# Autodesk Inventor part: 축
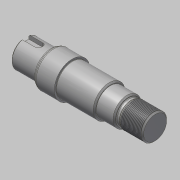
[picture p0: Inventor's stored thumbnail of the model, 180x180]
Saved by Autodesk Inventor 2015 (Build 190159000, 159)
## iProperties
Created: 2019-05
Part Number: 축
Material: 강철, 연강
Document SubType Name: Modeling
Designer: mduedu
Density: 1 g/cm^3
Appearance: 강철
Author: mduedu
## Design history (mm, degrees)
sketch "스케치1"
  geometry: L1 (0, 0)-(20, 0); L2 (20, 0)-(20, 11); L3 (20, 11)-(0, 11); L4 (0, 11)-(0, 0); L5 (20, 0)-(37, 0); L6 (37, 0)-(37, 14); L7 (37, 14)-(20, 14); L8 (20, 14)-(20, 0); L9 (37, 0)-(67, 0); L10 (67, 0)-(67, 12.5); L11 (67, 12.5)-(37, 12.5); L12 (37, 12.5)-(37, 0); L13 (67, 0)-(81, 0); L14 (81, 0)-(81, 11); L15 (81, 11)-(67, 11); L16 (67, 11)-(67, 0); L17 (81, 0)-(102, 0); L18 (102, 0)-(102, 10); L19 (102, 10)-(81, 10); L20 (81, 10)-(81, 0)
  constraints: 40 end point, 10 parallel, 5 horizontal, 5 perpendicular
  dimensions: "d0" = 102 distance between parallel lines of L18 L4; "d2" = 21 distance of L18.end L19.end; "d3" = 14 distance of L14.end L15.end; "d4" = 30 distance of L10.end L11.end; "d5" = 17 distance of L6.end L7.end; "d6" = 22 diameter of L3 L1; "d7" = 28 diameter of L7 L5; "d8" = 25 diameter of L11 L9; "d9" = 22 diameter of L15 L13; "d10" = 20 diameter of L19 L17
revolve "회전1" sketch "스케치1" stored, may be unused: angle "d11" = 90 deg
chamfer "모따기1" distance "d12" = 2.34; stored, may be unused: second distance "d13" = 2, angle "d14" = 30 deg
fillet "모깎기1" dims "d15" = 2, "d16" = 1
fillet "모깎기2" dims "d17" = 0.3
chamfer "모따기2" distance "d18" = 1; stored, may be unused: second distance "d19" = 2, angle "d20" = 30 deg
sketch "스케치2"
  geometry: L1 (102, -10)-(81, -10) reference; L2 (81, -10)-(81, -11) reference; L3 (81, -11)-(67, -11) reference; L4 (67, -11)-(67, -11.5) reference; L5 (67, -11.5)-(66, -12.5) reference; L6 (66, -12.5)-(37.3, -12.5) reference; L7 (37, -12.8)-(37, -14) reference; L8 (37, -14)-(22.876, -14) reference; L9 (21.876, -13.732)-(20.5, -12.938) reference; L10 (20, -12.072)-(20, -11) reference; L11 (20, -11)-(0, -11) reference; L12 (0, -11)-(0, 11) reference; L13 (0, 11)-(20, 11) reference; L14 (20, 11)-(20, 12.072) reference; L15 (20.5, 12.938)-(21.876, 13.732) reference; L16 (22.876, 14)-(37, 14) reference; L17 (37, 14)-(37, 12.8) reference; L18 (37.3, 12.5)-(66, 12.5) reference; L19 (66, 12.5)-(67, 11.5) reference; L20 (67, 11.5)-(67, 11) reference; L21 (67, 11)-(81, 11) reference; L22 (81, 11)-(81, 10) reference; L23 (81, 10)-(102, 10) reference; L24 (102, 10)-(102, -10) reference; L25 (0, 0)-(102, 0); L26 (81, 10)-(84.726, 10); L27 (83.34, 9.2)-(81, 9.2); L28 (81, 9.2)-(81, 10); L29 (84.726, 10)-(83.34, 9.2); A1 r 0.3 centre (37.3, -12.8) between (37.3, -12.5) and (37, -12.8) reference; A2 r 2 centre (22.876, -12) between (21.876, -13.732) and (22.876, -14) reference; A3 r 1 centre (21, -12.072) between (20, -12.072) and (20.5, -12.938) reference; A4 r 1 centre (21, 12.072) between (20.5, 12.938) and (20, 12.072) reference; A5 r 2 centre (22.876, 12) between (22.876, 14) and (21.876, 13.732) reference; A6 r 0.3 centre (37.3, 12.8) between (37, 12.8) and (37.3, 12.5) reference
  constraints: 10 end point, 1 horizontal, 1 midpoint, 1 parallel, 1 vertical
  dimensions: "d21" = 18.4 diameter of L27 L25; "d23" = 2.34 distance of L27.start L27.end; "d24" = 30 deg angle of L23 L29
revolve "회전2" sketch "스케치2" stored, may be unused: angle "d25" = 90 deg
fillet "모깎기3" dims "d26" = 0.6
chamfer "모따기3" distance "d27" = 1; stored, may be unused: second distance "d28" = 2, angle "d29" = 30 deg
feature "스레드1" dims "d30" = 10, "d31" = 0
chamfer "모따기4" distance "d32" = 1; stored, may be unused: second distance "d33" = 2, angle "d34" = 30 deg
node "작업 평면1"
sketch "스케치3"
  geometry: L1 (10, -3)-(-1, -3); L2 (-1, -3)-(-1, 3); L3 (-1, 3)-(10, 3); L4 (10, 3)-(10, -3); 3 further points
  constraints: 8 end point, 2 midpoint, 2 parallel, 1 coincident, 1 horizontal, 1 perpendicular, 1 vertical alignment, 2 other
  dimensions: "d35" = 14 dimension on L4; "d37" = 6 distance between parallel lines of L3 L1
extrude "돌출1" cut sketch "스케치3" distance "d38" = 3.5; taper "d39" = 0 deg
chamfer "모따기5" distance "d40" = 1; stored, may be unused: second distance "d41" = 2, angle "d42" = 30 deg
node "솔리드1"
node "절단 모서리 투영1"
